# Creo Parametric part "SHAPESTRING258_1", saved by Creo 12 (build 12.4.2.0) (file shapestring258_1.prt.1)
Units: Custom; MM, KILOGRAM, SECS

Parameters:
  PTC_WM_ITERATION = "0"
  PTC_WM_VERSION = "-.0"
  PTC_WM_LIFECYCLE_STATE = "In Work"
  PTC_WM_LIFECYCLE = "MO_CADDocument"
  PTC_WM_CREATED_BY = "Maximilian Roepper (Z0017RMS: MO)"
  PTC_WM_CREATED_ON = "18-Sep-26 11:36:42 AM"
  PTC_WM_MODIFIED_BY = "Maximilian Roepper (Z0017RMS: MO)"
  PTC_WM_MODIFIED_ON = "18-Sep-26 11:36:46 AM"
  PDMLINKNUMBER = "PDM000071455212"
  PTC_WM_NAME = "shapestring258_1.prt"
  PTC_WM_NUMBER = "PDM000071455212"

Other parameters: WEIGHT, WEIGHT_FACTOR, WEIGHT_ADD, _MASS_TEMP, _DIFF_TEMP, MC_ERRORS, SUPPLIER

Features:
  1. coordinate system
  2. datum plane "PRT_YZ"
  3. datum plane "PRT_XY"
  4. datum plane "PRT_XZ"
  5. coordinate system
  6. datum axis
  7. datum axis
  8. datum axis
  9. coordinate system
  10. imported feature
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
Other named items: PRT, SIEMENS_MO, DRW_VIEW_ORG, PRT_X, PRT_Y, PRT_Z, CS0, ROUGH_GROB

Layers: 00_STD_CSYS-KSYS, 01_STD_PLANES-EBENEN, 02_STD_AXES-ACHSEN, 03_STD_CSYS-KSYS, 24_IMPORT_FEAT-IMPORT_KE, WHITE

Surfaces: 1 plane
